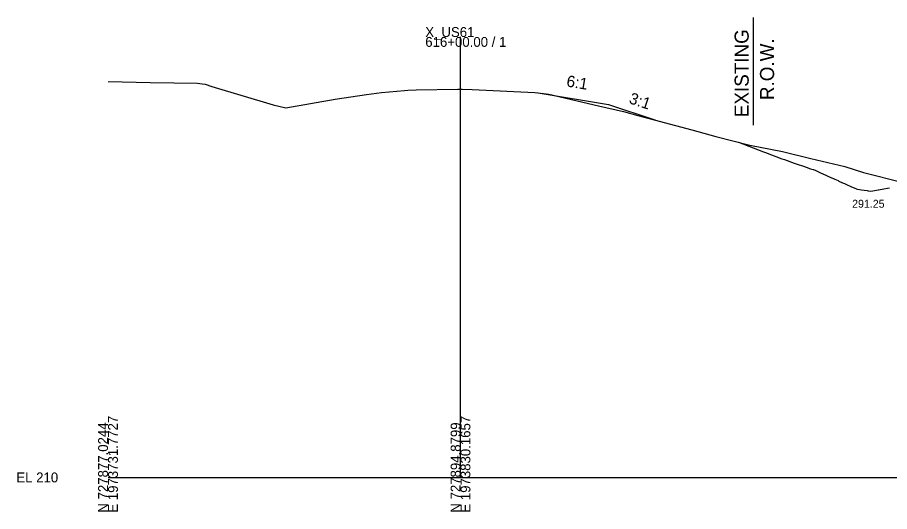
# Model space of a CAD drawing. Extents: x -26 to 1604, y -13 to 9623.
# Drawn here: x 974.3 to 1221.7, y -9.7 to 130.5 of the extents above; entities that cross this region are included whole.
import ezdxf

# ---------------------------------------------------------------- set-up
doc = ezdxf.new("R2010")
doc.units = 0
for name, color, linetype in [('Default', 7, 'Continuous'), ('Draft_XS_Grid', 7, 'Continuous'), ('DTM CONTOURS_MAJOR', 7, 'Continuous'), ('DTM_X_GROUND', 7, 'Continuous'), ('SLOPE_STAKES_FILL', 7, 'Continuous'), ('XS_CELL', 7, 'Continuous'), ('XS_P_GROUND', 7, 'Continuous'), ('XS_P_TX_DCH', 7, 'Continuous'), ('XS_P_TX_FS_BS', 7, 'Continuous'), ('XS_X_ROW', 7, 'Continuous')]:
    doc.layers.add(name, color=color, linetype=linetype)

msp = doc.modelspace()

# ---------------------------------------------------------------- linework, layer by layer
at = {"layer": 'DTM_X_GROUND'}
msp.add_lwpolyline([(1000, 112.34), (1011.92, 112.1), (1025.34, 111.85), (1026.67, 111.7), (1027.54, 111.6), (1029.49, 110.9), (1046.82, 105.77), (1050.45, 104.86), (1064.42, 107.33), (1073.29, 108.68), (1077.59, 109.22), (1084.12, 109.84), (1085.04, 109.88), (1087.46, 109.99), (1099.28, 110.18), (1100.47, 110.2), (1103.35, 110.07), (1121.07, 109.28), (1123.54, 108.96), (1125.04, 108.76), (1139.16, 105.45), (1146.22, 103.82), (1150.34, 102.71), (1165.63, 98.69), (1172.39, 96.8), (1182.1, 94.3), (1191.34, 92.45), (1199.36, 90.53), (1208.98, 88.27), (1214.32, 86.55), (1225.59, 83.67)], dxfattribs=at)
at = {"layer": 'XS_CELL'}
for p, q in [((1100, 0), (1100, 125)), ((1000, 0), (1100, 0)), ((1100, 0), (1600, 0))]:
    msp.add_line(p, q, dxfattribs=at)
at = {"layer": 'XS_P_GROUND'}
for points in [[(1122, 109.16), (1142, 105.83)], [(1142, 105.83), (1155.09, 101.47)], [(1178.81, 95.15), (1185.99, 92.39), (1186.52, 92.19), (1191.14, 90.46), (1191.88, 90.19), (1194.66, 89.19), (1195.46, 88.9), (1197.26, 88.29), (1198.06, 88.01), (1199.27, 87.62), (1200.06, 87.37), (1200.07, 87.37), (1200.1, 87.36), (1200.77, 87.06), (1200.97, 86.97), (1202.31, 86.37), (1202.56, 86.25), (1204.02, 85.6), (1204.16, 85.54), (1205.73, 84.84), (1205.76, 84.83), (1206.17, 84.64), (1207.12, 84.22), (1207.35, 84.11), (1208.39, 83.65), (1208.95, 83.4), (1209.67, 83.08), (1210.54, 82.69), (1210.95, 82.51), (1212.14, 81.98), (1212.23, 81.94), (1212.59, 81.78), (1213.73, 81.62), (1214.52, 81.51), (1215.33, 81.4), (1215.65, 81.36), (1216.44, 81.25)], [(1216.44, 81.25), (1216.92, 81.34), (1218.45, 81.61), (1218.52, 81.62), (1218.56, 81.63), (1220.11, 81.9), (1221.08, 82.07), (1221.71, 82.18)]]:
    msp.add_lwpolyline(points, dxfattribs=at)
at = {"layer": 'XS_X_ROW'}
msp.add_line((1183, 130.55), (1183, 100), dxfattribs=at)

# ---------------------------------------------------------------- texts
at = {"layer": 'Default'}
for p in [(1141.96, 105.77), (1212.55, 81.72)]:
    msp.add_text('X', height=0.12, dxfattribs=at).set_placement(p)
at = {"layer": 'Draft_XS_Grid'}
msp.add_text('-', height=0.0001, dxfattribs=at).set_placement((1000, 0))
at = {"layer": 'DTM CONTOURS_MAJOR'}
for p in [(1206.13, 84.58), (1216.4, 81.19), (1216.4, 81.19)]:
    msp.add_text('X', height=0.12, dxfattribs=at).set_placement(p)
at = {"layer": 'SLOPE_STAKES_FILL'}
msp.add_text('X', height=0.12, dxfattribs=at).set_placement((1141.96, 105.77))
at = {"layer": 'XS_CELL'}
for s, p in [('X_US61', (1090, 125)), ('616+00.00 / 1', (1090, 122.2)), ('EL 210', (974, -1.4))]:
    msp.add_text(s, height=2.8, dxfattribs=at).set_placement(p)
for s, p in [('N 727877.0244', (1000, -10)), ('E 1973731.7727', (1002.8, -10)), ('N 727894.8799', (1100, -10)), ('E 1973830.1657', (1102.8, -10))]:
    msp.add_text(s, height=2.8, rotation=90, dxfattribs=at).set_placement(p)
at = {"layer": 'XS_P_GROUND'}
for p in [(1121.96, 109.1), (1155.05, 101.41)]:
    msp.add_text('X', height=0.12, dxfattribs=at).set_placement(p)
at = {"layer": 'XS_P_TX_DCH'}
msp.add_text('291.25', height=2.25, dxfattribs=at).set_placement((1211.09, 76.54))
at = {"layer": 'XS_P_TX_FS_BS'}
for s, rotation, p in [('6:1', 350.5377, (1129.89, 110.98)), ('3:1', 341.5651, (1147.58, 106.26))]:
    msp.add_text(s, height=3.24, rotation=rotation, dxfattribs=at).set_placement(p)
at = {"layer": 'XS_X_ROW'}
for s, p in [('EXISTING', (1181.75, 102.24)), ('R.O.W.', (1188.95, 107.08))]:
    msp.add_text(s, height=4, rotation=90, dxfattribs=at).set_placement(p)

doc.saveas('drawing.dxf')
